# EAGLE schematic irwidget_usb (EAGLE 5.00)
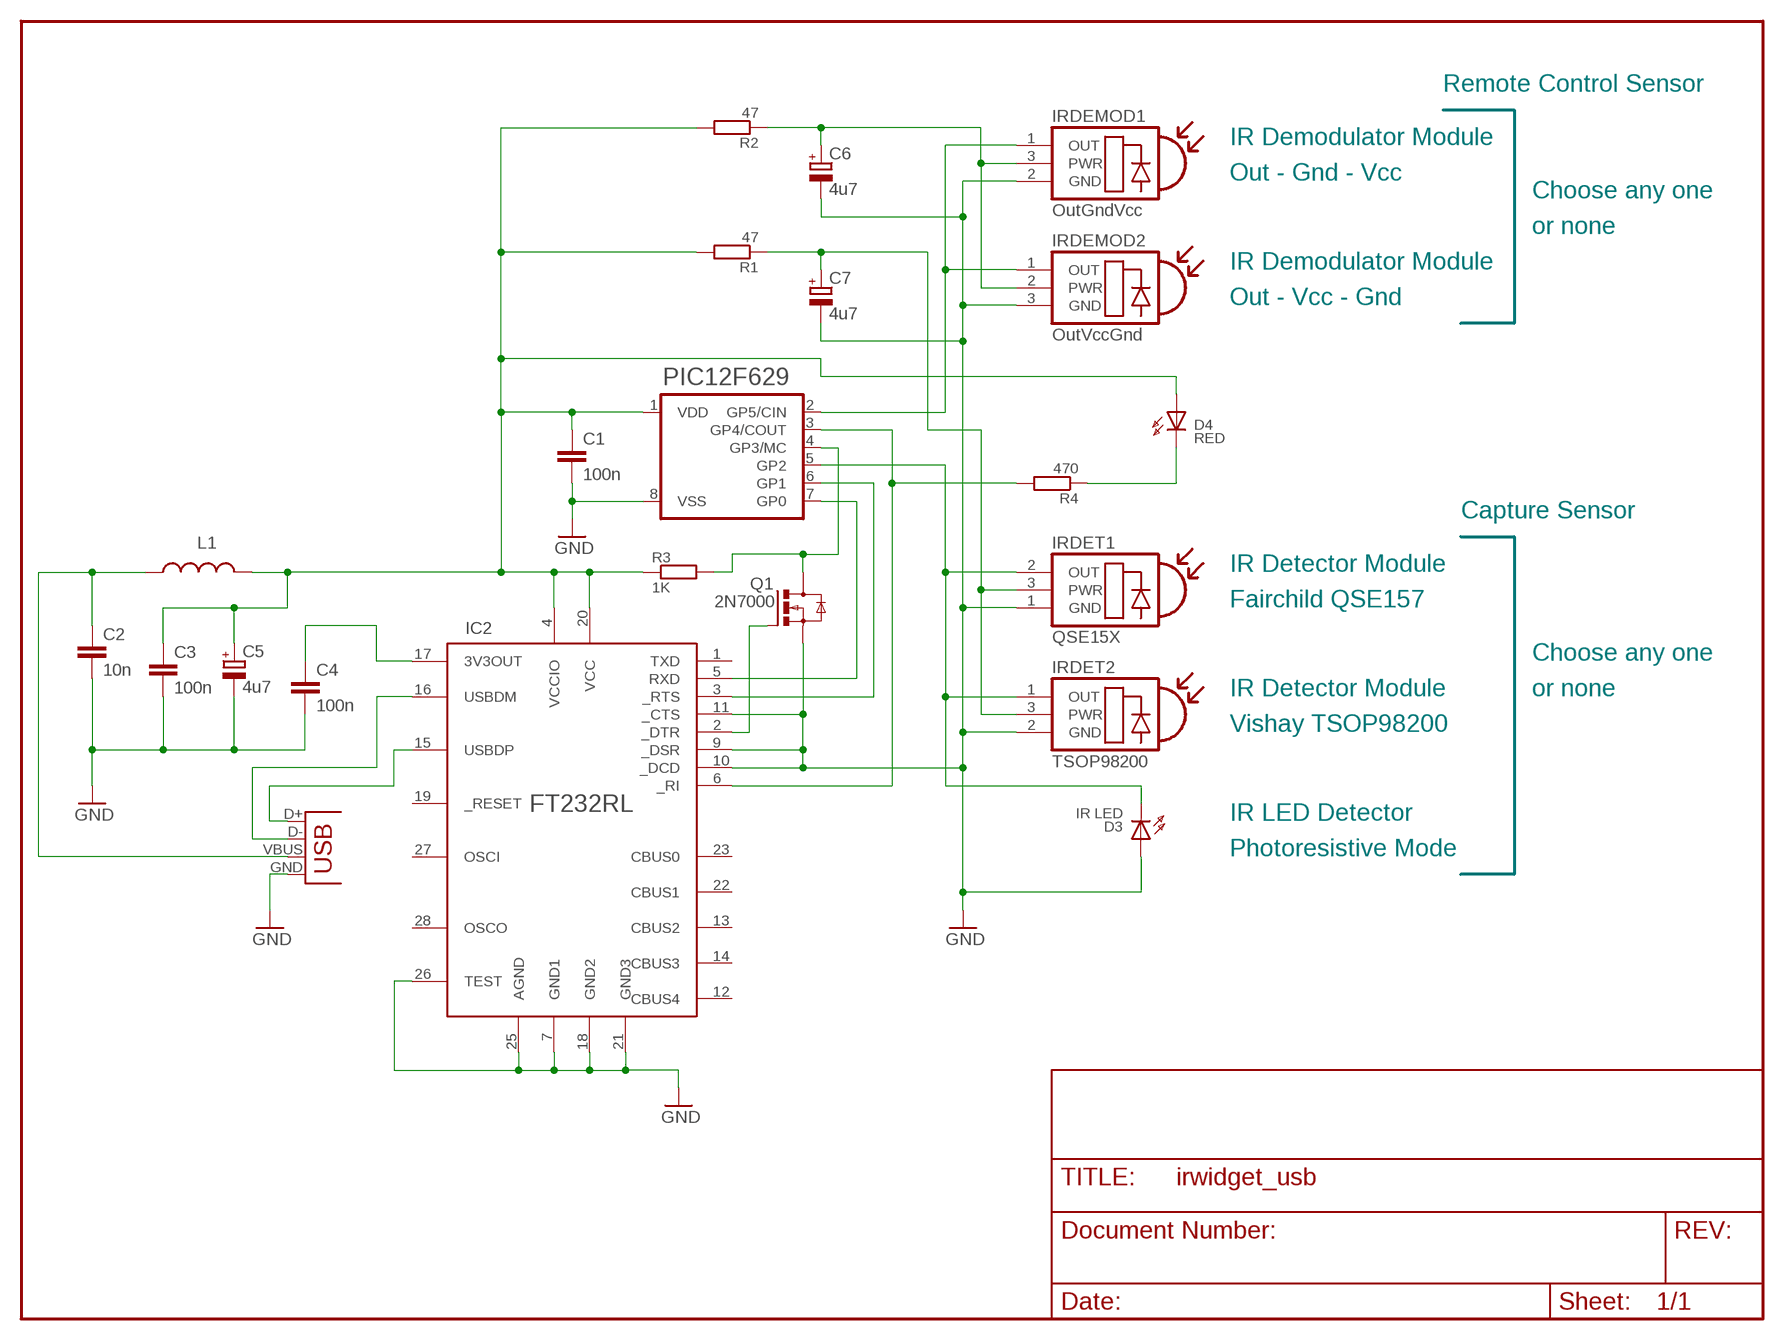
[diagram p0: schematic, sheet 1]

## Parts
C1  100n  C-EU025-025X050  [C025-025X050]
C2  10n  C-EU025-025X050  [C025-025X050]
C3  100n  C-EU025-025X050  [C025-025X050]
C4  100n  C-EU025-025X050  [C025-025X050]
C5  4u7  CPOL-EU085CS-1AW  [085CS_1AW]
C6  4u7  CPOL-EU085CS-1AW  [085CS_1AW]
C7  4u7  CPOL-EU085CS-1AW  [085CS_1AW]
D3  IR LED  LED5  [LED5]
D4  RED  LED5  [LED5]
IC1  12F629  12C509P  [DIL8]
IC2  FT232RL  [SSOP28DB]
IRDEMOD1  OutGndVcc  IRDM-OGP  [IRDM-OGP]
IRDEMOD2  OutVccGnd  IRDM-OPG  [IRDM-OPG]
IRDET1  QSE15X  [IRDET]
IRDET2  TSOP98200  IRDM-OGP  [IRDM-OGP]
L1  INDUCTOR0603  [0603]
Q1  2N7000  [TO92-]
R1  47  EW30  [EW30]
R2  47  EW30  [EW30]
R3  1K  EW30  [EW30]
R4  470  EW30  [EW30]
X1  USBSMD  [USB-MINIB]

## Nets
GND: C1.2 C2.2 C3.2 C4.2 C5.- C6.- C7.- D3.A IC1.8(VSS) IC2.7(GND1) IC2.9(_DSR) IC2.10(_DCD) IC2.11(_CTS) IC2.18(GND2) IC2.21(GND3) IC2.25(AGND) IC2.26(TEST) IRDEMOD1.2(GND) IRDEMOD2.3(GND) IRDET1.1(GND) IRDET2.2(GND) Q1.3(S) X1.GND
N$1: C6.+ IRDEMOD1.3(PWR) IRDEMOD2.2(PWR) R2.1
N$2: C7.+ IRDET1.3(PWR) IRDET2.3(PWR) R1.1
N$3: IC1.2(GP5/CIN) IRDEMOD1.1(OUT) IRDEMOD2.1(OUT)
N$4: D4.K R4.1
N$5: IC1.7(GP0) IC2.5(RXD)
N$6: IC2.2(_DTR) Q1.2(G)
N$7: IC1.6(GP1) IC2.3(_RTS)
N$9: C1.1 C3.1 C5.+ D4.A IC1.1(VDD) IC2.4(VCCIO) IC2.20(VCC) L1.2 R1.2 R2.2 R3.1
N$10: IC2.15(USBDP) X1.D+
N$11: C2.1 L1.1 X1.VBUS
N$12: IC2.16(USBDM) X1.D-
N$13: IC1.4(GP3/MC) Q1.1(D) R3.2
N$14: C4.1 IC2.17(3V3OUT)
N$15: D3.K IC1.5(GP2) IRDET1.2(OUT) IRDET2.1(OUT)
RI: IC1.3(GP4/COUT) IC2.6(_RI) R4.2
Unconnected: IC2.1(TXD) IC2.12(CBUS4) IC2.13(CBUS2) IC2.14(CBUS3) IC2.19(_RESET) IC2.22(CBUS1) IC2.23(CBUS0) IC2.27(OSCI) IC2.28(OSCO)

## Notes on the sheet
- Remote Control Sensor
- IR Demodulator Module
- Out - Gnd - Vcc
- Choose any one
- or none
- IR Demodulator Module
- Out - Vcc - Gnd
- PIC12F629
- Capture Sensor
- IR Detector Module
- Fairchild QSE157
- Choose any one
- IR Detector Module | or none
- Vishay TSOP98200
- FT232RL
- IR LED Detector
- Photoresistive Mode

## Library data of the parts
C1-C4 = rcl:C-EU: CAPACITOR, European symbol
C5-C7 = rcl:CPOL-EU: POLARIZED CAPACITOR, European symbol
D3 D4 = led:LED5
IC1 = pic:12C509P
IC2 = SparkFun:FT232RL: USB UART FT232RL 4th Generation USB UART (USB <-> Serial) Controller. Spark Fun Electronics SKU : COM-00650
IRDEMOD1 IRDET2 = my_ir_mo:IRDM-OGP
IRDEMOD2 = my_ir_mo:IRDM-OPG
IRDET1 = my_ir_mo:QSE15X
L1 = SparkFun:INDUCTOR: Inductors
Q1 = my_trans:2N7000
R1-R4 = my_resis:EW30
X1 = SparkFun:USB: USB Connectors USB-B-PTH is fully proven SKU : PRT-00139 USB-miniB is fully proven SKU : PRT-00587 USB-A-PCB is untested. USB-A-H is throughly reviewed, but untested. Spark Fun Electronics SKU : PRT-00437 USB-B-SMT is throughly reviewed, but untested. Needs silkscreen touching up. USB-A-S has not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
